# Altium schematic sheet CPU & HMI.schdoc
size 257 x 122 mm
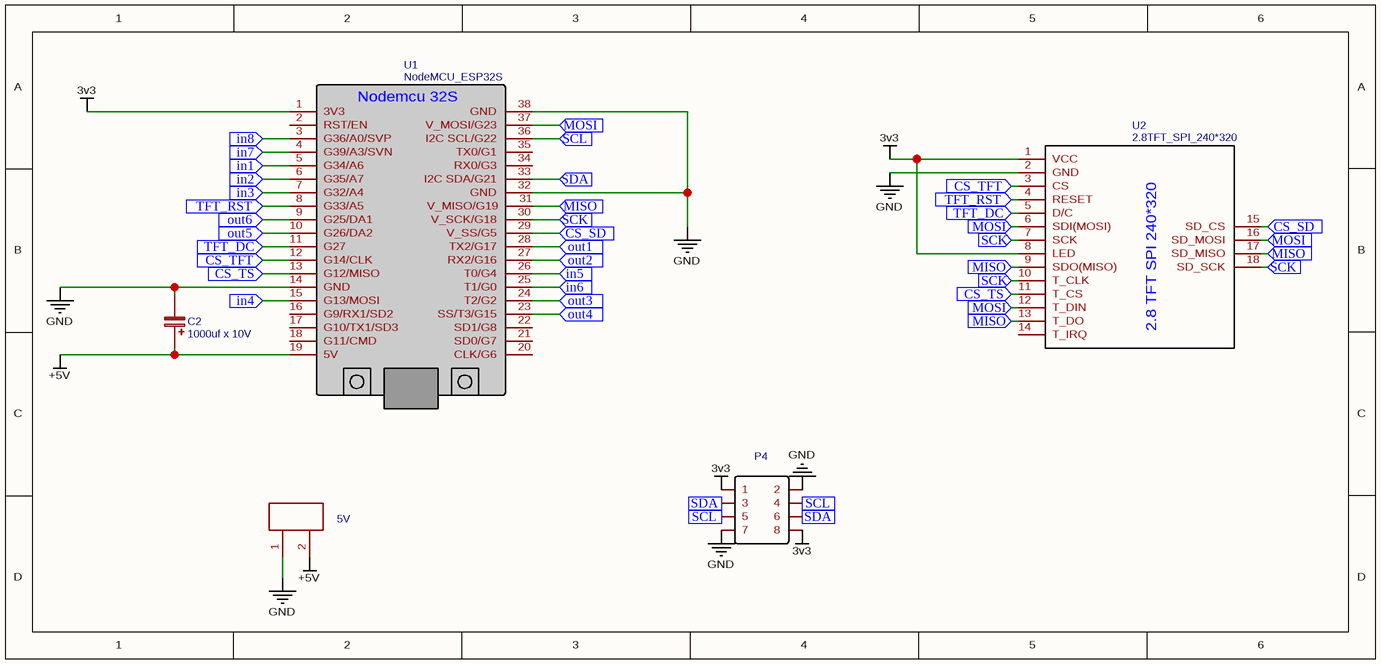
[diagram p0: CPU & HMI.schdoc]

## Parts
5V  Terminal 2 Poles 5.12mm  [BORNERA 2 PINES]  (value not drawn)
C2  1000uf x 10V  [CAP-D8.0XF3.5]
P4  HDR-IDC-2.54-2X4P (optional i2C expansion)  [HDR-IDC-2.54-2X4P]  (value not drawn)
U1  NodeMCU_ESP32S  [NODEMCU-ESP32S]
U2  2.8TFT_SPI_240*320  [2.8TFT_SPI_240*320]

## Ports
CS_SD (in), CS_TFT (in), CS_TS (in), in1 (in), in2 (in), in3 (in), in4 (in), in5 (in), in6 (in), in7 (in), in8 (in), MISO (in), MOSI (in), out1 (in), out2 (in), out3 (in), out4 (in), out5 (in), out6 (in), SCK (in), SCL (in), SDA (in), TFT_DC (in), TFT_RST (in)

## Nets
3v3: P4.1 P4.8 U1.1(3V3) U2.1(VCC) U2.8(LED)
+5V: 5V.2 C2.1 U1.19(5V)
GND: 5V.1 C2.2 P4.2 P4.7 U1.14(GND) U1.32(GND) U1.38(GND) U2.2(GND)
CS_SD: U1.29(V_SS/G5) U2.15(SD_CS) ; port CS_SD
CS_TFT: U1.12(G14/CLK) U2.3(CS) ; port CS_TFT
CS_TS: U1.13(G12/MISO) U2.11(T_CS) ; port CS_TS
in1: U1.5(G34/A6) ; port in1
in2: U1.6(G35/A7) ; port in2
in3: U1.7(G32/A4) ; port in3
in4: U1.15(G13/MOSI) ; port in4
in5: U1.26(T0/G4) ; port in5
in6: U1.25(T1/G0) ; port in6
in7: U1.4(G39/A3/SVN) ; port in7
in8: U1.3(G36/A0/SVP) ; port in8
MISO: U1.31(V_MISO/G19) U2.9(SDO(MISO)) U2.13(T_DO) U2.17(SD_MISO) ; port MISO
MOSI: U1.37(V_MOSI/G23) U2.6(SDI(MOSI)) U2.12(T_DIN) U2.16(SD_MOSI) ; port MOSI
out1: U1.28(TX2/G17) ; port out1
out2: U1.27(RX2/G16) ; port out2
out3: U1.24(T2/G2) ; port out3
out4: U1.23(SS/T3/G15) ; port out4
out5: U1.10(G26/DA2) ; port out5
out6: U1.9(G25/DA1) ; port out6
SCK: U1.30(V_SCK/G18) U2.7(SCK) U2.10(T_CLK) U2.18(SD_SCK) ; port SCK
SCL: P4.4 P4.5 U1.36(I2C_SCL/G22) ; port SCL
SDA: P4.3 P4.6 U1.33(I2C_SDA/G21) ; port SDA
TFT_DC: U1.11(G27) U2.5(D/C) ; port TFT_DC
TFT_RST: U1.8(G33/A5) U2.4(RESET) ; port TFT_RST

Not connected (* = marked no-connect by the designer): U1 2(RST/EN) 16(G9/RX1/SD2) 17(G10/TX1/SD3) 18(G11/CMD) 20(CLK/G6) 21(SD0/G7) 22(SD1/G8) 34(RX0/G3) 35(TX0/G1); U2 14(T_IRQ)

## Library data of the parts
5V = Terminal 2 Poles 5.12mm: BOM_Manufacturer Part: BORNERA CIRCUITO IMPRESO 2PINES; Contributor: capoelectronics
C2 = 1000uf x 10V: nameAlias: Value(F); Contributor: EasyEDA
P4 = HDR-IDC-2.54-2X4P (optional i2C expansion): BOM_Manufacturer: BOOMELE; BOM_Manufacturer Part: IDC Box 2X4 2.54MM
U1 = NodeMCU_ESP32S: BOM_Manufacturer Part: NodeMCU ESP32S; Contributor: JUAN GUALBERTO ESPIRITU MARCELIANO
U2 = 2.8TFT_SPI_240*320: Contributor: dmiljkov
